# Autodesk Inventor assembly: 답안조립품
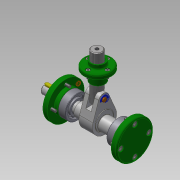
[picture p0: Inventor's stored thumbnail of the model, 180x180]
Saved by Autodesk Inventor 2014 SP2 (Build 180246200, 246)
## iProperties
Created: 2016-08
Part Number: 답안조립품
Document SubType Name: Assembly
Designer: user
Author: user
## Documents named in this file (15)
- C:\Users\user\Desktop\460820V1022\답안조립품.iam
- C:\Users\user\Desktop\460820V1022\본체.ipt
- C:\Users\user\Desktop\460820V1022\편심축.ipt
- C:\Users\user\Desktop\460820V1022\베어링 15 x 35 x 11.ipt
- C:\Users\user\Desktop\460820V1022\앞커버.ipt
- C:\Users\user\Desktop\460820V1022\뒤커버.ipt
- C:\Users\user\Desktop\460820V1022\볼트 M4 x 10.ipt
- C:\Users\user\Desktop\460820V1022\오일실 15 25 7.ipt
- C:\Users\user\Desktop\460820V1022\링크.ipt
- C:\Users\user\Desktop\460820V1022\슬라이드바.ipt
- C:\Users\user\Desktop\460820V1022\상부부시.ipt
- C:\Users\user\Desktop\460820V1022\볼트 M3 x 8.ipt
- C:\Users\user\Desktop\460820V1022\키 5 x 5 x 14.ipt
- C:\Users\user\Desktop\460820V1022\멈춤링 6 x 5.ipt
- C:\Users\user\Desktop\460820V1022\고정핀.ipt
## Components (13 placed, 3 different names)
1. ISO 4762 M4 x 10:1 — 강체:4
2. ISO 4762 M4 x 10:2 — 강체:3
3. ISO 4762 M4 x 10:3 — 강체:2
4. ISO 4762 M4 x 10:4 — 강체:1
5. ISO 4762 M4 x 10:5 — 강체:6
6. ISO 4762 M4 x 10:6 — 강체:5
7. ISO 4762 M4 x 10:7 — 강체:7
8. ISO 4762 M4 x 10:8 — 강체:8
9. ISO 4762 M3 x 8:1 — 강체:11
10. ISO 4762 M3 x 8:2 — 강체:9
11. ISO 4762 M3 x 8:3 — 강체:10
12. ISO 4762 M3 x 8:4 — 강체:12
13. 고정핀:1
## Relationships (12: WeldJoint 12)
- 강체:1 [WeldJoint]: ISO 4762 M4 x 10:4
- 강체:2 [WeldJoint]: ISO 4762 M4 x 10:3
- 강체:3 [WeldJoint]: ISO 4762 M4 x 10:2
- 강체:4 [WeldJoint]: ISO 4762 M4 x 10:1
- 강체:5 [WeldJoint]: ISO 4762 M4 x 10:6
- 강체:6 [WeldJoint]: ISO 4762 M4 x 10:5
- 강체:7 [WeldJoint]: ISO 4762 M4 x 10:7
- 강체:8 [WeldJoint]: ISO 4762 M4 x 10:8
- 강체:9 [WeldJoint]: ISO 4762 M3 x 8:2
- 강체:10 [WeldJoint]: ISO 4762 M3 x 8:3
- 강체:11 [WeldJoint]: ISO 4762 M3 x 8:1
- 강체:12 [WeldJoint]: ISO 4762 M3 x 8:4
